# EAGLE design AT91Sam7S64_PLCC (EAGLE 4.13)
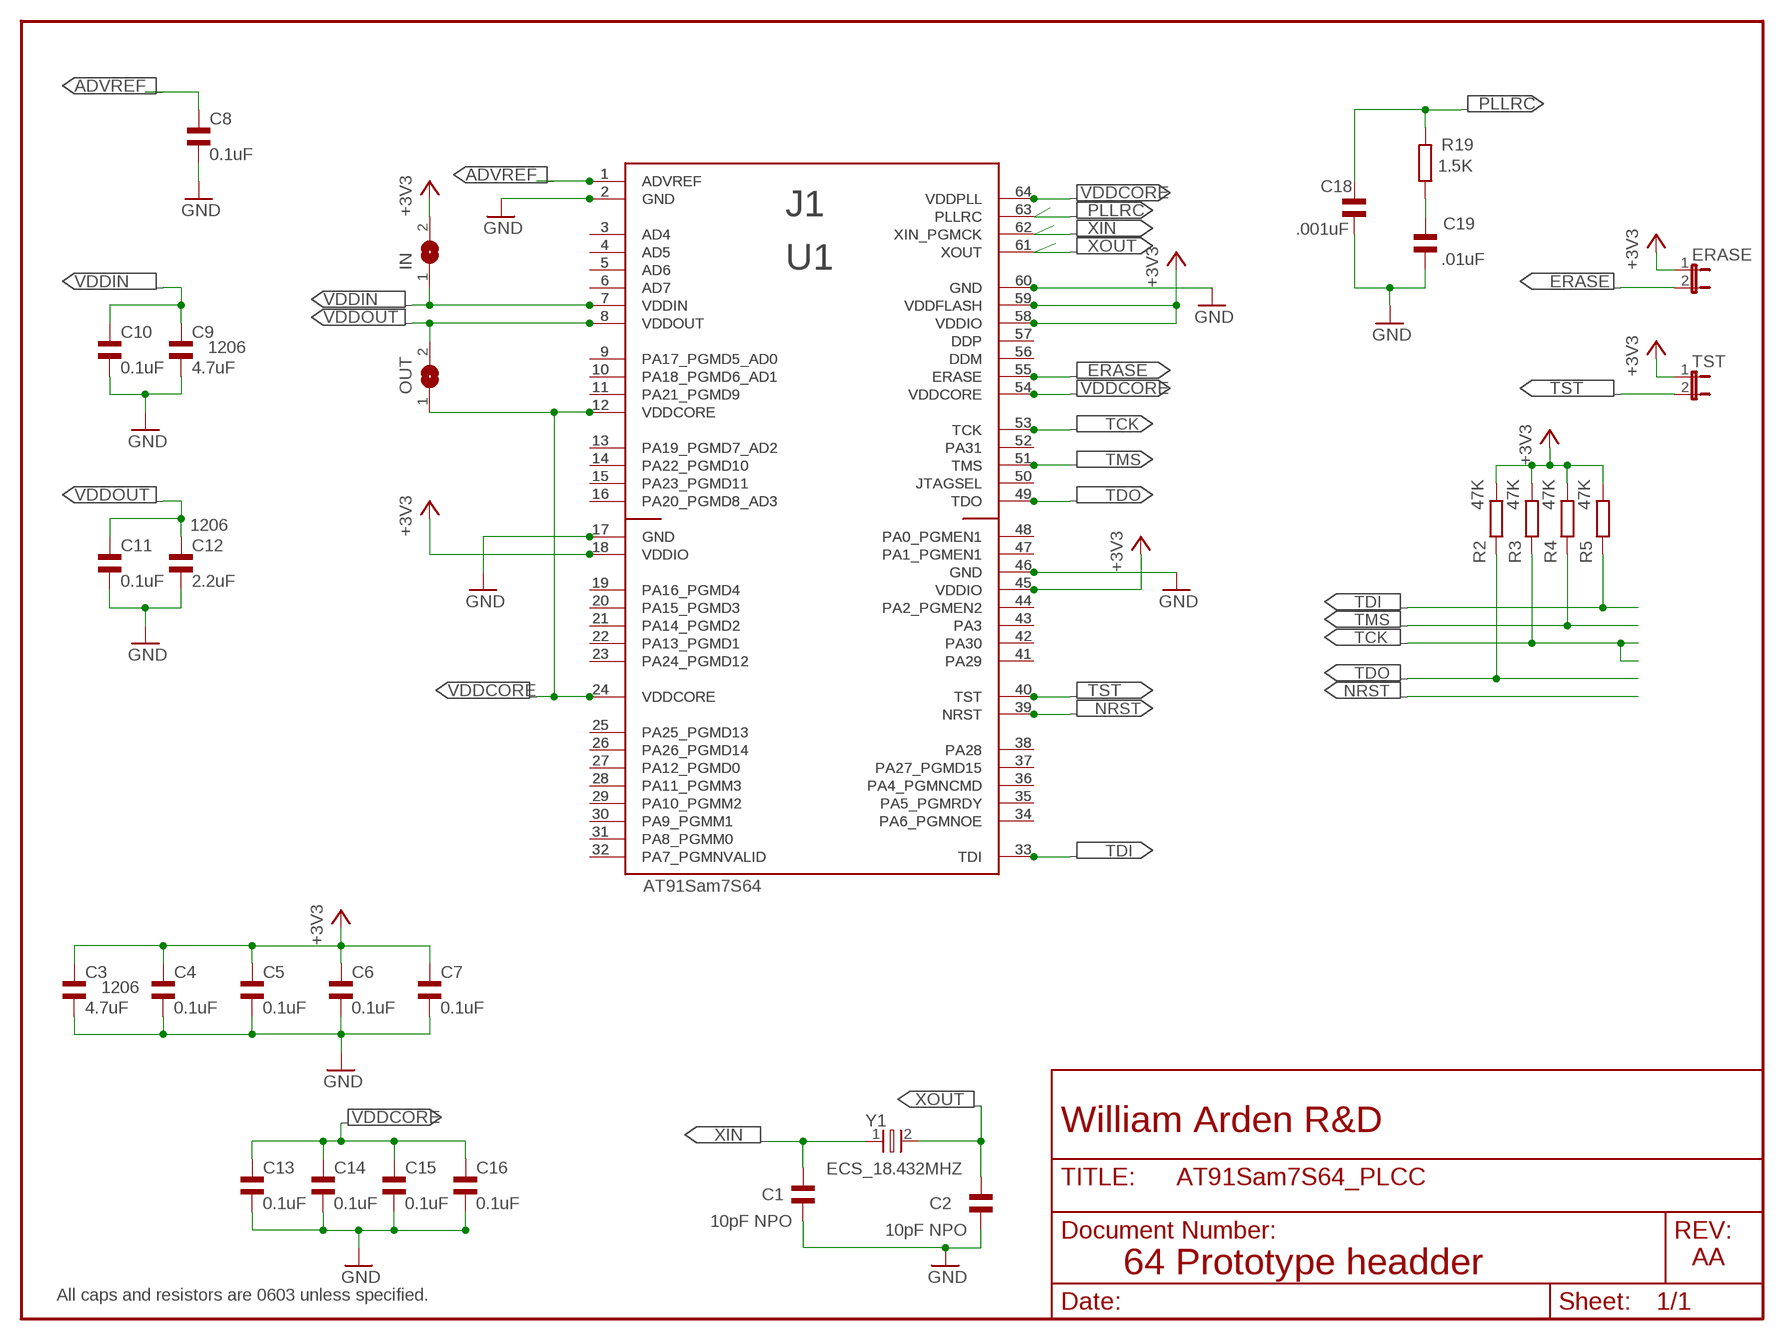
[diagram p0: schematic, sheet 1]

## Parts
C1  10pF NPO  C0603  [C0603]
C2  10pF NPO  C0603  [C0603]
C3  4.7uF  C1206  [C1206]
C4  0.1uF  C0603  [C0603]
C5  0.1uF  C0603  [C0603]
C6  0.1uF  C0603  [C0603]
C7  0.1uF  C0603  [C0603]
C8  0.1uF  C0603  [C0603]
C9  4.7uF  C1206  [C1206]
C10  0.1uF  C0603  [C0603]
C11  0.1uF  C0603  [C0603]
C12  2.2uF  C1206  [C1206]
C13  0.1uF  C0603  [C0603]
C14  0.1uF  C0603  [C0603]
C15  0.1uF  C0603  [C0603]
C16  0.1uF  C0603  [C0603]
C18  .001uF  C0603  [C0603]
C19  .01uF  C0603  [C0603]
ERASE  JP1E  [JP1]
IN  SJ  [SJ]
J1  AT91Sam7S64  AT91SAM7S64_PLCC64_43  [HEADER_PLCC64_43]
OUT  SJ  [SJ]
R2  47K  R0603  [R0603]
R3  47K  R0603  [R0603]
R4  47K  R0603  [R0603]
R5  47K  R0603  [R0603]
R19  1.5K  R0603  [R0603]
TST  JP1E  [JP1]
U1  AT91SAM7S64_LQFP64  [LQFP64]
Y1  ECS_18.432MHZ  XTALECS_8MHZ  [XTAL-ECS]

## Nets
+3V3: C3.2 C4.2 C5.2 C6.2 C7.2 ERASE.1 IN.2 J1.18(VDDIO) J1.45(VDDIO) J1.58(VDDIO) J1.59(VDDFLASH) R2.2 R3.2 R4.2 R5.2 TST.1 U1.18(VDDIO) U1.45(VDDIO) U1.58(VDDIO) U1.59(VDDFLASH)
ADVREF: C8.2 J1.1(ADVREF) U1.1(ADVREF)
DDM: J1.56(DDM) U1.56(DDM)
DDP: J1.57(DDP) U1.57(DDP)
ERASE: ERASE.2 J1.55(ERASE) U1.55(ERASE)
GND: C1.1 C2.1 C3.1 C4.1 C5.1 C6.1 C7.1 C8.1 C9.1 C10.1 C11.1 C12.1 C13.1 C14.1 C15.1 C16.1 C18.1 C19.1 J1.2(GND) J1.17(GND) J1.46(GND) J1.60(GND) U1.2(GND) U1.17(GND) U1.46(GND) U1.60(GND)
JTAGSEL: J1.50(JTAGSEL) U1.50(JTAGSEL)
N$4: C19.2 R19.1
N$22: J1.3(AD4) U1.3(AD4)
N$24: J1.4(AD5) U1.4(AD5)
N$25: J1.5(AD6) U1.5(AD6)
N$28: J1.6(AD7) U1.6(AD7)
N$39: J1.9(PA17_PGMD5_AD0) U1.9(PA17_PGMD5_AD0)
N$40: J1.32(PA7_PGMNVALID) U1.32(PA7_PGMNVALID)
N$41: J1.31(PA8_PGMM0) U1.31(PA8_PGMM0)
N$42: J1.30(PA9_PGMM1) U1.30(PA9_PGMM1)
N$43: J1.29(PA10_PGMM2) U1.29(PA10_PGMM2)
N$44: J1.28(PA11_PGMM3) U1.28(PA11_PGMM3)
N$45: J1.27(PA12_PGMD0) U1.27(PA12_PGMD0)
N$46: J1.26(PA26_PGMD14) U1.26(PA26_PGMD14)
N$47: J1.25(PA25_PGMD13) U1.25(PA25_PGMD13)
N$48: J1.42(PA30) U1.42(PA30)
N$49: J1.41(PA29) U1.41(PA29)
N$52: J1.38(PA28) U1.38(PA28)
N$53: J1.37(PA27_PGMD15) U1.37(PA27_PGMD15)
N$54: J1.36(PA4_PGMNCMD) U1.36(PA4_PGMNCMD)
N$55: J1.35(PA5_PGMRDY) U1.35(PA5_PGMRDY)
N$57: J1.16(PA20_PGMD8_AD3) U1.16(PA20_PGMD8_AD3)
N$58: J1.15(PA23_PGMD11) U1.15(PA23_PGMD11)
N$59: J1.14(PA22_PGMD10) U1.14(PA22_PGMD10)
N$60: J1.13(PA19_PGMD7_AD2) U1.13(PA19_PGMD7_AD2)
N$62: J1.11(PA21_PGMD9) U1.11(PA21_PGMD9)
N$63: J1.10(PA18_PGMD6_AD1) U1.10(PA18_PGMD6_AD1)
N$65: J1.44(PA2_PGMEN2) U1.44(PA2_PGMEN2)
N$67: J1.47(PA1_PGMEN1) U1.47(PA1_PGMEN1)
N$68: J1.48(PA0_PGMEN1) U1.48(PA0_PGMEN1)
N$76: J1.23(PA24_PGMD12) U1.23(PA24_PGMD12)
N$77: J1.52(PA31) U1.52(PA31)
N$78: J1.21(PA14_PGMD2) U1.21(PA14_PGMD2)
N$80: J1.22(PA13_PGMD1) U1.22(PA13_PGMD1)
N$82: J1.19(PA16_PGMD4) U1.19(PA16_PGMD4)
N$84: J1.34(PA6_PGMNOE) U1.34(PA6_PGMNOE)
N$85: J1.43(PA3) U1.43(PA3)
N$86: J1.20(PA15_PGMD3) U1.20(PA15_PGMD3)
NRST: J1.39(NRST) U1.39(NRST)
PLLRC: C18.2 R19.2 U1.63(PLLRC)
TCK: J1.53(TCK) R3.1 U1.53(TCK)
TDI: J1.33(TDI) R5.1 U1.33(TDI)
TDO: J1.49(TDO) R2.1 U1.49(TDO)
TMS: J1.51(TMS) R4.1 U1.51(TMS)
TST: J1.40(TST) TST.2 U1.40(TST)
UNUSED1: J1.63(PLLRC)
UNUSED2: J1.62(XIN_PGMCK)
UNUSED3: J1.61(XOUT)
VDDCORE: C13.2 C14.2 C15.2 C16.2 J1.12(VDDCORE) J1.24(VDDCORE) J1.54(VDDCORE) J1.64(VDDPLL) OUT.1 U1.12(VDDCORE) U1.24(VDDCORE) U1.54(VDDCORE) U1.64(VDDPLL)
VDDIN: C9.2 C10.2 IN.1 J1.7(VDDIN) U1.7(VDDIN)
VDDOUT: C11.2 C12.2 J1.8(VDDOUT) OUT.2 U1.8(VDDOUT)
XIN: C1.2 U1.62(XIN_PGMCK) Y1.1
XOUT: C2.2 U1.61(XOUT) Y1.2

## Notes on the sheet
- 1206
- 1206
- 1206
- William Arden R&D
- AA
- 64 Prototype headder
- All caps and resistors are 0603 unless specified.

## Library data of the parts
C1 C2 C4-C8 C10 C11 C13-C16 C18 C19 = ipc-rcl:C0603
C3 C9 C12 = ipc-rcl:C1206
ERASE TST = jumper:JP1E: JUMPER
IN OUT = jumper:SJ: SMD solder JUMPER
J1 U1 = Atmel_Prototype_Header:AT91SAM7S64: Atmel AT91 ARM Thumb-based Microcontroller. LQFP64 package.
R2-R5 R19 = ipc-rcl:R0603
Y1 = 0_Darren:XTAL: CRYSTAL 8.00MHZ 18PF SMD , Example: ECS, Inc. Part # ECS-80-18-5P-TR

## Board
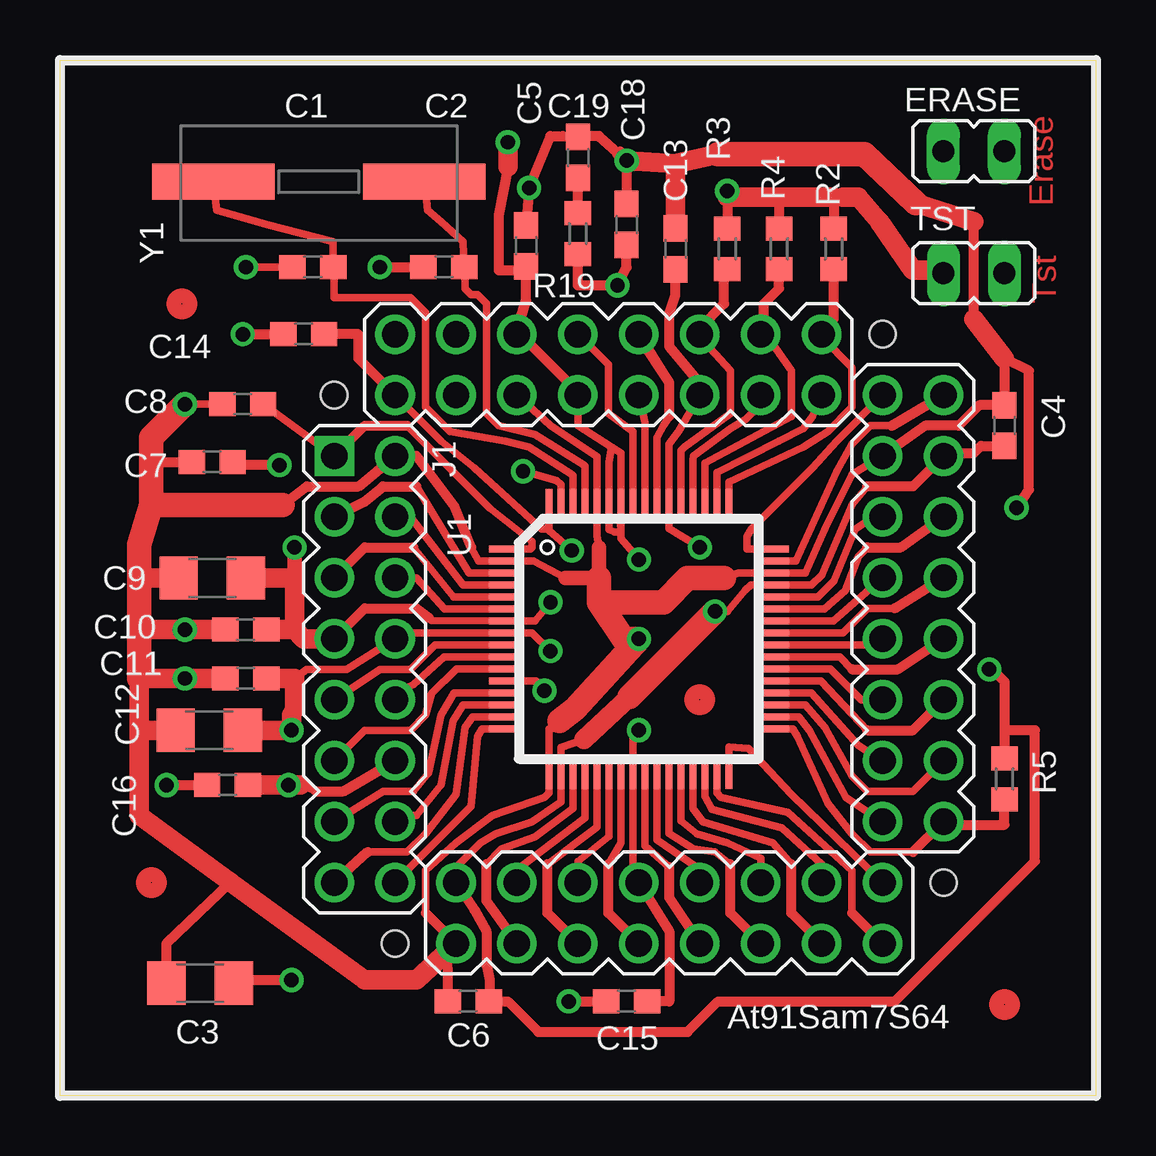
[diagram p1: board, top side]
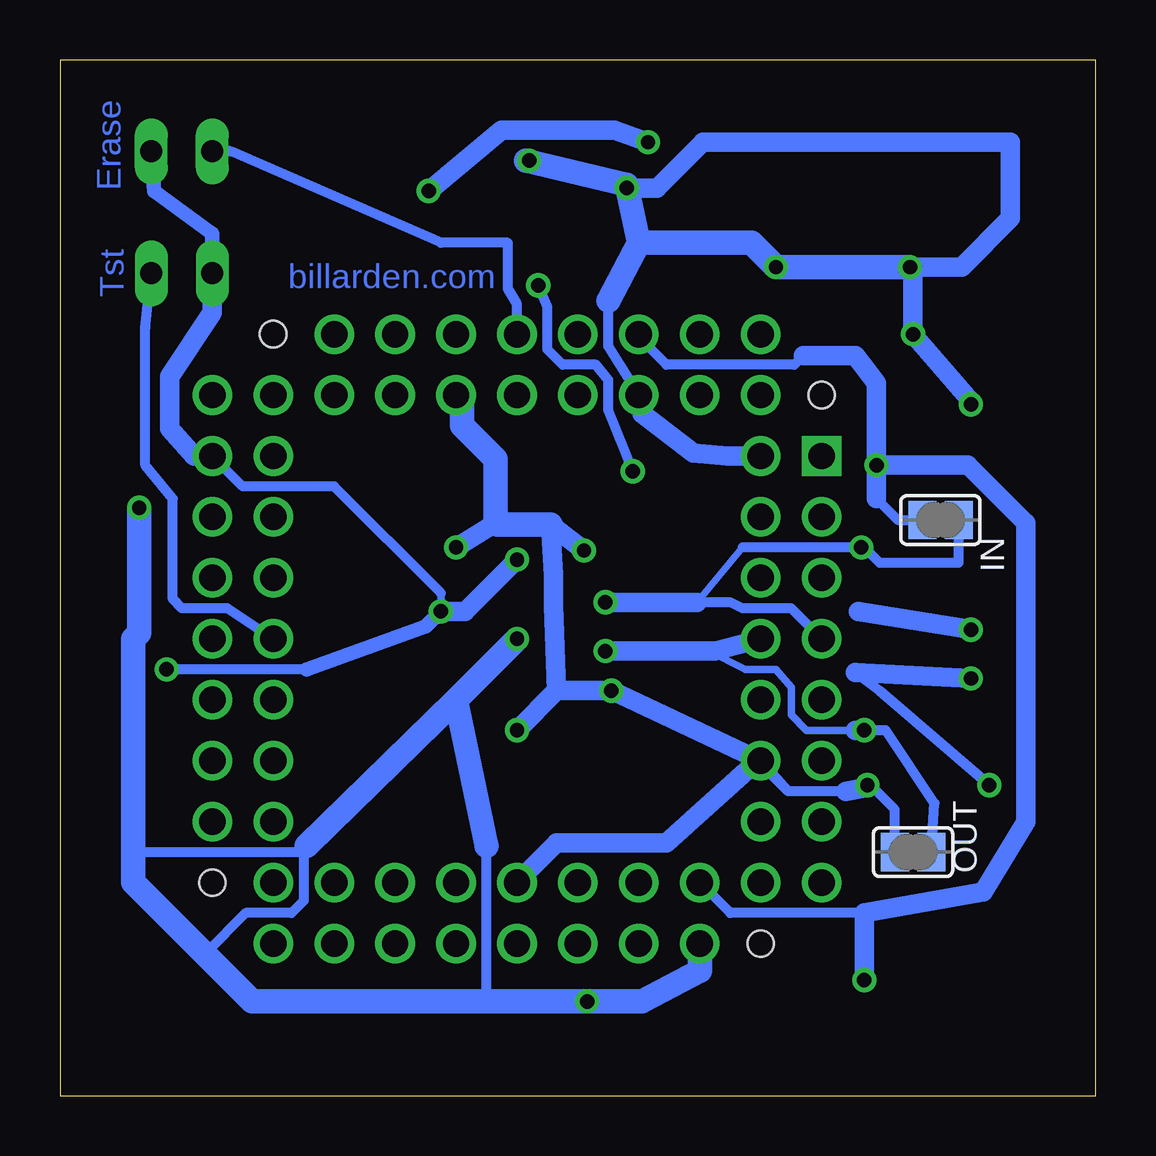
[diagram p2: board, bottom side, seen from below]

Size 43.18 x 43.18 mm. Coordinates in mm from the lower left corner, seen from the top.
Outline: 0,0 0,43.18 43.18,43.18 43.18,0 0,0
Copper layers (1*2+15*16): Top 0.035mm / dielectric 0.5mm / NotUsed 0.035mm / dielectric 0.5mm / Notused 0.035mm / dielectric 0.5mm / Bottom 0.035mm
Design rules "RestringMinZero": minimum track width 6mil, minimum drill 12mil, track to track 7mil, track to pad 7mil, pad to pad 7mil, via to via 8mil, smd to smd 8mil, copper to edge 0mil, drill to drill 8mil, minimum pad ring 0mil, minimum via ring 8mil, stop-mask expansion 0mil, vias tented up to drill 20mil, thermal gap 12mil
vRestrict: 4 lines

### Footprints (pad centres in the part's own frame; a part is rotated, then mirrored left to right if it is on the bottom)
C0603 = smd 1.1 x 1: 1 -0.85,0; 2 0.85,0
C1206 = smd 1.6 x 1.8: 1 -1.4,0; 2 1.4,0
JP1 = drill 0.914 long: 1 0,-1.27; 2 0,1.27
SJ = smd 1.168 x 1.6: 1 -0.762,0; 2 0.762,0
HEADER_PLCC64_43 = drill 1.1 square: 1 -12.7,7.62 | drill 1.1 round: 2 -10.16,7.62; 3 -12.7,5.08; 4 -10.16,5.08; 5 -12.7,2.54; 6 -10.16,2.54; 7 -12.7,0; 8 -10.16,0; 9 -12.7,-2.54; 10 -10.16,-2.54; 11 -12.7,-5.08; 12 -10.16,-5.08; 13 -12.7,-7.62; 14 -10.16,-7.62; 15 -12.7,-10.16; 16 -10.16,-10.16; 17 -7.62,-12.7; 18 -7.62,-10.16; 19 -5.08,-12.7; 20 -5.08,-10.16; 21 -2.54,-12.7; 22 -2.54,-10.16; 23 0,-12.7; 24 0,-10.16; 25 2.54,-12.7; 26 2.54,-10.16; 27 5.08,-12.7; 28 5.08,-10.16; 29 7.62,-12.7; 30 7.62,-10.16; 31 10.16,-12.7; 32 10.16,-10.16; 33 12.7,-7.62; 34 10.16,-7.62; 35 12.7,-5.08; 36 10.16,-5.08; 37 12.7,-2.54; 38 10.16,-2.54; 39 12.7,0; 40 10.16,0; 41 12.7,2.54; 42 10.16,2.54; 43 12.7,5.08; 44 10.16,5.08; 45 12.7,7.62; 46 10.16,7.62; 47 12.7,10.16; 48 10.16,10.16; 49 7.62,12.7; 50 7.62,10.16; 51 5.08,12.7; 52 5.08,10.16; 53 2.54,12.7; 54 2.54,10.16; 55 0,12.7; 56 0,10.16; 57 -2.54,12.7; 58 -2.54,10.16; 59 -5.08,12.7; 60 -5.08,10.16; 61 -7.62,12.7; 62 -7.62,10.16; 63 -10.16,12.7; 64 -10.16,10.16 | hole 1.1: -12.7,10.16; 10.16,12.7; 12.7,-10.16; -10.16,-12.7
R0603 = smd 1 x 1.1: 1 -0.85,0; 2 0.85,0
LQFP64 = smd 1.1 x 0.285: 1 -5.7,3.75; 2 -5.7,3.25; 3 -5.7,2.75; 4 -5.7,2.25; 5 -5.7,1.75; 6 -5.7,1.25; 7 -5.7,0.75; 8 -5.7,0.25; 9 -5.7,-0.25; 10 -5.7,-0.75; 11 -5.7,-1.25; 12 -5.7,-1.75; 13 -5.7,-2.25; 14 -5.7,-2.75; 15 -5.7,-3.25; 16 -5.7,-3.75; 33 5.7,-3.75; 34 5.7,-3.25; 35 5.7,-2.75; 36 5.7,-2.25; 37 5.7,-1.75; 38 5.7,-1.25; 39 5.7,-0.75; 40 5.7,-0.25; 41 5.7,0.25; 42 5.7,0.75; 43 5.7,1.25; 44 5.7,1.75; 45 5.7,2.25; 46 5.7,2.75; 47 5.7,3.25; 48 5.7,3.75 | smd 0.285 x 1.1: 17 -3.75,-5.7; 18 -3.25,-5.7; 19 -2.75,-5.7; 20 -2.25,-5.7; 21 -1.75,-5.7; 22 -1.25,-5.7; 23 -0.75,-5.7; 24 -0.25,-5.7; 25 0.25,-5.7; 26 0.75,-5.7; 27 1.25,-5.7; 28 1.75,-5.7; 29 2.25,-5.7; 30 2.75,-5.7; 31 3.25,-5.7; 32 3.75,-5.7; 49 3.75,5.7; 50 3.25,5.7; 51 2.75,5.7; 52 2.25,5.7; 53 1.75,5.7; 54 1.25,5.7; 55 0.75,5.7; 56 0.25,5.7; 57 -0.25,5.7; 58 -0.75,5.7; 59 -1.25,5.7; 60 -1.75,5.7; 61 -2.25,5.7; 62 -2.75,5.7; 63 -3.25,5.7; 64 -3.75,5.7
XTAL-ECS = smd 5.1 x 1.5: 1 -4.4,0; 2 4.4,0

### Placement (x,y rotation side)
C1  10.54,34.54 0 top
C2  16,34.54 0 top
C3  5.84,4.7 0 top
C4  39.37,27.94 270 top
C5  19.43,35.43 270 top
C6  17.02,3.94 0 top
C7  6.35,26.42 0 top
C8  7.62,28.83 0 top
C9  6.35,21.59 0 top
C10  7.75,19.43 0 top
C11  7.75,17.4 0 top
C12  6.22,15.24 0 top
C13  25.65,35.31 270 top
C14  10.16,31.75 0 top
C15  23.62,3.94 0 top
C16  6.99,12.95 0 top
C18  23.62,36.32 270 top
C19  21.59,39.12 270 top
ERASE  38.1,39.37 90 top
IN  6.48,24 180 bottom
J1  24.13,19.05 0 top
OUT  7.62,10.16 0 bottom
R2  32.26,35.31 90 top
R3  27.81,35.31 90 top
R4  29.97,35.31 90 top
R5  39.37,13.21 90 top
R19  21.59,35.94 270 top
TST  38.1,34.29 270 top
U1  24.13,19.05 0 top
U$1  [DRAWING]  not placed on the board
U$3  [FIDUCIAL]  39.37,3.81 0 top
U$4  [FIDUCIAL]  3.81,8.89 0 top
U$5  [FIDUCIAL]  26.67,16.51 0 top
U$10  [FIDUCIAL]  5.08,33.02 0 top
Y1  10.79,38.1 0 top

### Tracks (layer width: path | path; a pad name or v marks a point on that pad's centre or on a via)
+3V3  (via drill 0.6)
  Top 0.305: 22.99,27.05 23.38,26.79 U1.58 23.38,23.51 | 22.99,27.05 21.59,27.94 J1.58 | 22.99,27.05 22.88,26.4 | 21.84,14.86 20.88,14.53 U1.18 20.88,12.24 19.68,11.43 18.16,10.92 17.53,10.54 16.64,9.65 J1.18 | 23.38,23.51 23.37,23.88 | 23.38,23.51 23.11,23.5 22.88,23.6 22.88,26.4 | 22.88,26.4 U1.59 | 23.38,23.51 23.38,23.23 v24.13,22.35 | v27.3,20.19 27.81,20.19 28.57,21.08 28.79,21.3 29.81,21.3 | J1.45 36.96,26.8 | U1.45 31.33,21.3 31.75,21.72 33.02,24.64 33.66,25.4
  Top 0.406: C4.2 38.39,27.09 38.1,26.8 36.96,26.8 | 33.66,25.4 35.56,25.4 J1.45 | J1.58 21.59,29.34 19.18,31.75 J1.59 19.05,31.88 19.43,33.15 C5.2 | C7.2 7.24,26.42 7.37,26.29 v9.14,26.29 | 29.97,36.07 R4.2 29.97,37.47 | 27.81,37.47 R3.2 | R2.2 32.26,37.47 32.64,37.47 | TST.1 36.96,34.42 | 19.3,34.42 18.29,34.42 18.29,36.7 18.67,38.73 | J1.18 17.27,7.75 17.78,6.86 17.78,5.46 17.91,4.83 17.91,4.06 C6.2 | C3.2 7.37,4.83 v9.65,4.83 | 39.37,15.24 40.64,15.24 40.64,9.78 34.8,3.94 27.43,3.94 26.16,2.67 19.94,2.67 18.67,3.94 C6.2 | C6.2 17.78,3.94 | v38.73,17.78 38.73,17.91 39.37,17.27 R5.2
  Top 0.813: 21.84,14.86 23.75,16.64 | 32.26,37.47 29.97,37.47 27.94,37.47 | 27.94,37.47 27.81,37.47 | 32.64,37.47 33.27,37.47 34.16,36.45 35.56,34.42 36.96,34.42 | v18.67,39.75 18.67,38.73 | 27.94,37.47 v27.81,37.72
  Top 1.016: 23.75,16.64 v27.3,20.19
  Bottom 0.305: v27.3,20.19 27.3,20.95
  Bottom 0.406: J1.45 35.56,25.4 31.75,25.4 27.3,20.95 | 32.89,17.78 v38.73,17.78 | J1.59 19.05,31.62 17.91,30.48 12.57,30.48 12.19,30.86 | IN.2 8.26,24 9.14,24.89 | ERASE.1 39.37,39.62 | J1.18 15.24,7.62 9.65,7.62
  Bottom 0.61: 32.89,17.78 27.94,19.56 v27.3,20.19 | TST.1 36.83,35.94 39.24,37.72 ERASE.1
  Bottom 0.813: v24.13,22.35 26.29,20.19 v27.3,20.19 | TST.1 36.83,32.64 38.61,29.97 38.61,27.81 37.59,26.67 J1.45 | 12.19,30.86 10.03,30.86 9.14,29.72 v9.14,26.29 | v9.14,26.29 9.14,24.89 | v18.67,39.75 20.07,40.26 24.77,40.26 v27.81,37.72 | v9.14,26.29 5.33,26.29 2.92,23.88 2.92,11.43 4.7,8.51 9.65,7.62 v9.65,4.83
ADVREF
  Top 0.305: U1.1 19.62,22.8 19.68,22.86 19.68,23.11 17.91,24.51 14.48,27.94 | C8.2 J1.1
  Top 0.406: 14.48,27.94 12.7,27.94 J1.1
DDM
  Top 0.305: U1.56 24.38,28.07 J1.56
DDP
  Top 0.305: U1.57 23.88,27.68 22.86,28.45 22.86,30.48 J1.57
ERASE
  Top 0.305: U1.55 24.88,27.43 25.15,27.94 25.4,28.32 | 24.13,31.62 J1.55
  Top 0.406: 25.4,28.32 25.4,29.72 | 25.4,29.72 24.13,31.62 | 25.4,29.72 J1.55
  Bottom 0.406: J1.55 24.13,33.02 24.51,33.66 24.51,35.56 27.3,35.56 36.07,39.37 ERASE.2
GND  (via drill 0.6)
  Top 0.305: J1.60 20.45,27.94 22.38,26.64 U1.60 22.38,23.34 22.48,22.86 | 21.08,21.59 19.74,22.3 U1.2 17.45,22.3 17.14,22.86 | 15.24,7.62 15.24,9.4 16.51,10.54 18.03,11.68 20.19,12.45 20.38,12.63 U1.17 20.38,15.3 20.57,15.37 | 27.69,21.59 28.28,21.8 U1.46 31.07,21.8 31.88,23.62 33.02,25.91 J1.46 | v5.21,28.83 C8.1 | v7.75,34.54 C1.1
  Top 0.406: 15.24,7.62 J1.17 16.64,6.35 16.13,5.84 C6.1 | 20.57,15.37 20.83,15.62 | J1.46 36.07,27.94 37.47,27.94 38.31,28.79 C4.1 39.37,30.73 40.39,30.23 40.39,25.27 v39.88,24.51 | v13.34,34.54 C2.1 | v23.62,38.99 C18.1 | v23.62,38.99 23.36,39.37 23.24,39.24 v23.62,38.99 | v23.62,38.99 22.48,40.01 21.21,40.01 C19.1 20.95,40.01 20.45,40.01 v19.56,37.85 C5.1 | v7.62,31.75 C14.1 | v4.45,12.95 C16.1 | 3.81,26.42 C7.1 | 9.27,24.64 10.29,25.4 12.45,25.4 J1.2 14.86,26.67 16.43,24.59 17.14,22.86 | v21.21,3.94 C15.1 | C3.1 4.45,6.35 7.11,8.89 7.12,8.9 | 38.1,32.38 38.1,36.45
  Top 0.61: 21.08,21.59 22.48,21.59 22.48,22.86
  Top 0.813: C10.1 v5.21,19.43 3.3,19.43 | C11.1 v5.21,17.4 3.3,17.4 3.3,15.24 | 3.3,15.24 C12.1 | 3.3,21.59 C9.1 | 25.65,38.86 C13.1 | 25.65,38.86 v23.62,38.99 | 27.43,39.24 25.65,38.86 | J1.17 14.86,4.83 12.7,4.83 7.12,8.9 3.3,11.68 3.3,15.24 | 39.37,30.73 38.1,32.38 | 38.1,36.45 35.69,37.21
  Top 1.016: 20.83,15.62 21.46,16.13 v24.13,19.05 23.5,19.05 22.48,20.57 | 22.48,20.57 22.48,21.59 | 27.69,21.59 26.16,21.59 25.15,20.57 22.48,20.57 | v5.21,28.83 3.81,27.43 3.81,26.42 3.81,24.64 | 3.81,24.64 3.3,22.99 3.3,21.59 3.3,19.43 3.3,17.4 | 3.81,24.64 9.27,24.64 | 35.69,37.21 33.53,39.24 27.43,39.24
  Bottom 0.305: 19.05,29.34 J1.60
  Bottom 0.406: 19.05,35.56 19.05,35.54 | 20.32,33.15 20.32,31.24 J1.60 | v5.21,28.83 5.33,28.83 | v4.45,12.95 9.02,16.89 10.03,17.65 | 40.13,10.16 33.27,10.16 32.38,10.92 | 32.89,10.41 33.02,10.16 33.02,8.13 33.53,7.62 35.43,7.62 37.08,5.97 | 25.4,3.94 25.4,10.41
  Bottom 0.813: v5.21,19.43 9.91,20.19 | v5.21,17.4 10.03,17.65 | J1.2 15.37,26.67 16.76,26.8 18.92,28.45 19.05,29.34 | v5.21,28.83 5.21,28.96 v7.62,31.75 7.62,34.42 v7.75,34.54 5.59,34.54 3.56,36.58 3.56,39.75 16.38,39.75 18.29,37.85 v19.56,37.85
  Bottom 1.016: v7.75,34.54 v13.34,34.54 14.35,35.56 19.05,35.56 20.32,33.15 | 19.05,35.54 19.56,37.97 | 19.56,37.97 v19.56,37.85 | J1.17 16.51,5.21 18.92,3.94 v21.21,3.94 25.4,3.94 35.18,3.94 40.13,8.89 40.13,10.16 40.13,19.05 39.88,19.3 v39.88,24.51 | 19.56,37.97 23.75,38.99 | 26.67,16.51 32.89,10.41 | 26.67,16.51 v24.13,19.05 | 25.4,10.41 26.67,16.51
JTAGSEL
  Top 0.305: U1.50 27.38,25.98 29.97,27.3 30.99,27.81 31.37,28.32 J1.50
N$4
  Top 0.406: R19.1 C19.2
N$22
  Top 0.305: U1.3 17.06,21.8 16,23.5 14.86,25.4
  Top 0.406: 14.86,25.4 13.46,25.4 12.7,24.77 J1.3
N$24
  Top 0.305: U1.4 16.8,21.3 14.61,24.13 J1.4
N$25
  Top 0.305: U1.5 16.41,20.8 14.73,22.86
  Top 0.406: 14.73,22.86 12.7,22.86 J1.5
N$28
  Top 0.305: U1.6 16.02,20.3 14.86,21.59 J1.6
N$39
  Top 0.305: U1.9 15.62,18.8 14.61,17.78 13.34,17.78 J1.9
N$40
  Top 0.305: U1.32 27.88,14.54 28.7,14.48 30.48,12.57 J1.32
N$41
  Top 0.305: U1.31 27.38,12.62 27.56,12.45 30.35,11.81 33.02,9.4 33.02,7.62
  Top 0.406: 33.02,7.62 J1.31
N$42
  Top 0.305: U1.30 26.88,12.49 27.18,11.94 30.1,11.18 31.75,9.65 J1.30
N$43
  Top 0.305: U1.29 26.38,11.97 26.8,11.43 29.72,10.54 30.48,9.65
  Top 0.406: 30.48,9.65 30.48,7.62 J1.29
N$44
  Top 0.305: U1.28 25.88,11.46 26.54,10.92 27.81,10.54 29.21,9.91 J1.28
N$45
  Top 0.305: U1.27 25.38,10.94 26.42,10.29 27.3,10.16 27.94,9.65
  Top 0.406: 27.94,9.65 27.94,7.62 J1.27
N$46
  Top 0.305: U1.26 24.88,11.95 24.89,11.81 24.89,10.67 26.54,9.53 26.67,9.4 J1.26
N$47
  Top 0.305: U1.25 24.38,10.42 25.4,9.53
  Top 0.406: 25.4,9.53 25.4,8.26 J1.25
N$48
  Top 0.305: U1.42 32.25,19.8 J1.42
N$49
  Top 0.305: U1.41 32.63,19.3 33.66,20.32 34.8,20.32
  Top 0.406: 34.8,20.32 J1.41
N$52
  Top 0.305: U1.38 32.11,17.8 33.4,16.51 J1.38
N$53
  Top 0.305: U1.37 31.72,17.3 33.66,15.24
  Top 0.406: 33.66,15.24 35.56,15.24 J1.37
N$54
  Top 0.305: U1.36 31.33,16.8 33.27,14.61 J1.36
N$55
  Top 0.305: U1.35 31.07,16.3 31.88,15.37 33.02,13.34 33.66,12.7 35.56,12.7 J1.35
N$57
  Top 0.305: U1.16 17.59,15.3 17.4,14.99 17.14,12.06 J1.16
N$58
  Top 0.305: U1.15 17.2,15.8 16.89,15.37 16.51,12.57 15.24,10.92 14.48,10.16 12.83,10.16
  Top 0.406: J1.15 12.83,10.16
N$59
  Top 0.305: U1.14 16.81,16.3 16.38,15.62 15.88,12.95 14.86,11.68 14.22,11.68 14.1,11.43 J1.14
N$60
  Top 0.305: U1.13 16.42,16.8 15.88,15.88 15.37,13.46 14.73,12.7 13.46,12.7 J1.13
N$62
  Top 0.305: U1.11 16.53,17.8 15.49,16.76 15.24,15.88 14.61,15.24 12.7,15.24 J1.11
N$63
  Top 0.305: U1.10 16.01,18.3 14.73,17.14 14.48,17.02 J1.10
N$65
  Top 0.305: U1.44 31.59,20.8 32.26,21.46 33.15,23.62 33.91,24.13 J1.44
N$67
  Top 0.305: U1.47 30.68,22.3 32.38,26.04 33.02,27.18 33.78,27.94 34.67,27.94
  Top 0.406: 34.67,27.94 J1.47
N$68
  Top 0.305: U1.48 28.64,22.8 28.64,23.31 28.83,23.62 31.37,26.16 32.38,27.3 J1.48
N$76
  Top 0.305: U1.23 23.38,10.55 22.86,9.65
  Top 0.406: 22.86,9.65 22.86,7.62 J1.23
N$77
  Top 0.305: J1.52 29.21,28.83 28.57,28.19 27.94,27.81 26.42,26.67 26.38,26.51 U1.52
N$78
  Top 0.305: U1.21 22.38,11.2 22.35,11.18 20.32,9.65
  Top 0.406: 20.32,9.65 20.32,7.62 J1.21
N$80
  Top 0.305: U1.22 22.88,10.81 21.59,9.78 J1.22
N$82
  Top 0.305: U1.19 21.38,11.98 19.81,10.79 18.41,10.29 17.78,9.65
  Top 0.406: 17.78,9.65 17.78,8.13 J1.19
N$84
  Top 0.305: U1.34 30.81,15.8 31.24,15.24 32.77,12.45 J1.34
N$85
  Top 0.305: U1.43 31.86,20.3 32.75,21.06 33.27,22.48 33.66,22.86
  Top 0.406: 33.66,22.86 35.05,22.86 J1.43
N$86
  Top 0.305: U1.20 21.88,11.59 19.18,9.53 J1.20
NRST
  Top 0.305: U1.39 32.5,18.3 33.02,17.78
  Top 0.406: 33.02,17.78 34.92,17.78 J1.39
PLLRC  (via drill 0.6)
  Top 0.305: U1.63 20.88,25.48 20.7,25.65 v19.3,26.04
  Top 0.406: R19.2 21.59,33.78 v23.24,33.78 23.62,34.54 C18.2
  Bottom 0.406: v19.3,26.04 20.32,28.57 20.32,29.84 20.83,30.48 22.23,30.48 22.86,31.11 22.86,32.89 v23.24,33.78
TCK
  Top 0.305: U1.53 25.88,26.9 26.04,27.05 27.94,28.45 27.94,30.23 26.67,31.62 J1.53
  Top 0.406: J1.53 26.67,32 27.69,33.02 27.69,34.16 27.81,34.29 R3.1
TDI
  Top 0.305: 35.56,10.16 33.78,10.16 33.02,10.92 32,12.19 30.73,14.99 30.55,15.3 U1.33 | J1.33 36.96,11.43 37.08,11.3
  Top 0.406: 35.56,10.16 J1.33 | R5.1 39.37,11.3 37.08,11.3
TDO
  Top 0.305: U1.49 27.88,25.59 30.99,27.05 32,27.69 33.02,28.7 33.02,30.35 31.75,31.62 J1.49
  Top 0.406: J1.49 31.75,31.88 32.26,32.38 R2.1
TMS
  Top 0.305: U1.51 26.88,26.37 30.48,28.32 30.48,30.23 29.59,31.5 J1.51
  Top 0.406: R4.1 29.97,33.66 29.34,33.02 29.34,31.88 J1.51
TST
  Top 0.305: U1.40 34.04,18.8 J1.40
  Bottom 0.406: J1.40 36.2,20.32 38.1,20.32 38.48,20.7 38.48,24.89 39.62,26.29 39.62,32 TST.2
VDDCORE  (via drill 0.6)
  Top 0.305: J1.54 25.78,27.69 25.38,27.18 U1.54 25.38,23.64 26.65,22.88 v26.67,22.86 | U1.12 19.84,17.3 19.84,17.24 v20.19,16.89 | v24.13,15.24 23.88,14.99 U1.24 23.88,9.39 24.13,9.14 J1.24 | v21.34,22.73 20.38,23.56 U1.64 20.38,23.81 20.32,23.62 20.07,23.62 17.27,26.16 15.88,27.3 J1.64 | 10.03,12.95 10.67,12.7
  Top 0.406: 10.67,12.7 11.81,12.7 J1.12 | J1.64 12.45,30.73 12.45,31.75 C14.2 | J1.54 26.67,29.72 25.4,31.24 25.4,32.64 25.65,33.4 C13.2 25.4,34.54 | J1.24 25.4,6.86 25.4,3.94 C15.2
  Top 0.813: C16.2 v9.53,12.95 10.03,12.95
  Bottom 0.406: 12.83,12.7 J1.12 | 10.41,12.7 12.83,12.7 | v9.53,12.95 9.4,12.95 8.38,11.94 OUT.1 | 12.83,12.7 14.1,13.97
  Bottom 0.813: v21.34,22.73 22.73,23.81 22.6,21.72 22.61,20.45 22.48,16.89 | 25.02,23.88 v26.67,22.86 | 22.48,16.89 v24.13,15.24 | 22.48,16.89 v20.19,16.89 J1.12 | 10.41,12.7 9.65,12.83 v9.53,12.95 | 14.1,13.97 17.91,10.54 22.48,10.54 J1.24
  Bottom 1.016: J1.54 26.42,28.96 26.42,27.94 25.02,26.54 25.02,23.88 24.95,23.81 22.73,23.81
VDDIN  (via drill 0.6)
  Top 0.305: 15.37,19.94 15.49,19.81 18.3,19.8 | U1.7 19.8,19.8 v20.45,20.57 | 9.78,21.84 9.65,21.72 9.65,21.59
  Top 0.406: 15.37,19.94 14.86,20.32 12.7,20.32 J1.7
  Top 0.61: 9.78,21.46 9.65,21.59 | 9.78,21.84 v9.78,22.86
  Top 0.813: J1.7 10.16,19.05 9.78,19.43 | C10.2 9.78,19.43 | 9.65,21.59 C9.2 | 9.78,19.43 9.78,21.46
  Bottom 0.305: 14.73,22.86 16.64,20.57
  Bottom 0.406: 16.64,20.57 15.24,20.57 14.73,20.32 12.7,20.32 J1.7 | 14.73,22.86 v9.78,22.86 9.65,22.86 9.02,22.23 5.71,22.23 IN.1
  Bottom 0.813: 16.64,20.57 v20.45,20.57
VDDOUT  (via drill 0.6)
  Top 0.305: U1.8 19.68,19.3 v20.44,18.54 | U1.8 | U1.8 16.01,19.3 16,19.3 14.35,19.3 14.1,19.05 J1.8 11.94,17.78 10.29,17.78 9.78,17.4
  Top 0.813: C12.2 v9.65,15.24 9.65,15.88 9.78,16.13 9.78,17.4 C11.2
  Bottom 0.305: 10.03,15.24 12.06,15.24 12.7,15.88 12.7,17.02 13.34,17.78 14.61,17.78 16.13,18.54 J1.8
  Bottom 0.406: OUT.2 6.73,12.19 8.76,15.24 v9.65,15.24
  Bottom 0.813: v20.44,18.54 15.88,18.54 J1.8 | v9.65,15.24 10.03,15.24
XIN
  Top 0.305: U1.62 21.38,25.86 21.34,25.91 19.56,27.05 18.54,27.3 16.26,27.69 15.24,28.7 15.24,32.64 14.61,33.27 11.43,33.27 11.43,34.42 11.39,34.46 C1.2 11.39,35.6 8.64,36.32 6.52,36.91 Y1.1
XOUT
  Top 0.305: U1.61 21.88,26.25 21.84,26.29 19.81,27.56 18.29,27.94 17.78,28.45 17.78,33.02 17.4,33.4 17.14,33.4 16.89,33.66 16.89,34.54 | C2.2 16.8,35.6 15.88,36.45 15.32,36.91 Y1.2
  Top 0.406: 16.89,34.54 C2.2

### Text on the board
Top: Erase | Tst
Bottom: Erase | billarden.com | Tst | IN | OUT
tNames: At91Sam7S64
